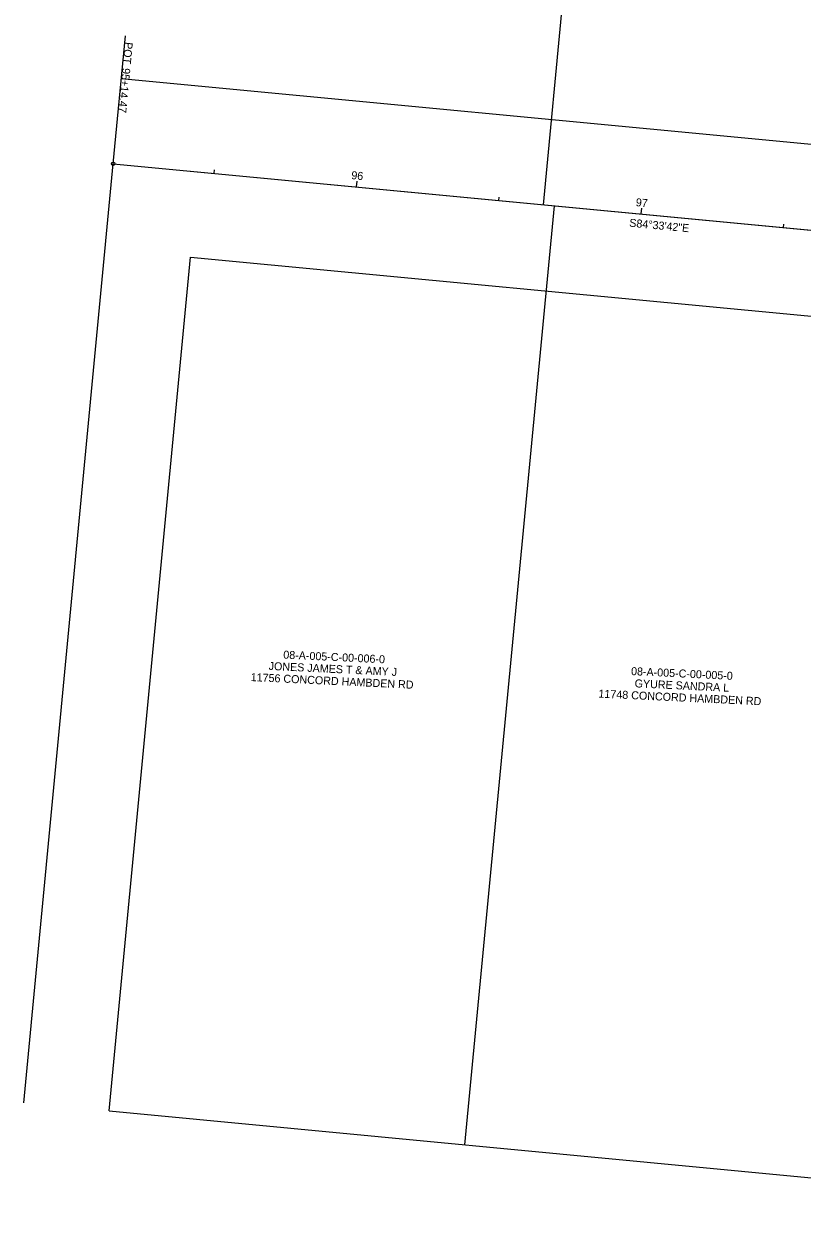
# Model space of a CAD drawing. Extents: x 2318731 to 2320621, y 732958 to 734198.
# Drawn here: x 2318820.8 to 2319093.1, y 733213.9 to 733628.7 of the extents above; entities that cross this region are included whole.
import ezdxf

# ---------------------------------------------------------------- set-up
doc = ezdxf.new("R2010")
doc.units = 0
for name, color, linetype in [('RW_X_CL_100_Bearings', 7, 'Continuous'), ('RW_X_CL_100_Cardinal_Points', 7, 'Continuous'), ('RW_X_CL_100_Stations', 7, 'Continuous'), ('RW_X_CL_500_Bearings', 7, 'Continuous'), ('RW_X_CL_500_Cardinal_Points', 7, 'Continuous'), ('RW_X_CL_500_Stations', 7, 'Continuous'), ('RW_X_Text', 7, 'Continuous'), ('SC_Scratch4', 7, 'Continuous'), ('V-SURV-IPF', 7, 'Continuous'), ('V-SURV-PARL-LINE', 7, 'Continuous'), ('V-SURV-RWAY', 7, 'Continuous')]:
    doc.layers.add(name, color=color, linetype=linetype)

msp = doc.modelspace()

# ---------------------------------------------------------------- linework, layer by layer
at = {"layer": 'RW_X_CL_100_Cardinal_Points'}
msp.add_line((2318852.08, 733579.68), (2318856.35, 733624.48), dxfattribs=at)
msp.add_circle((2318852.08, 733579.68), 0.6, dxfattribs=at)
at = {"layer": 'RW_X_CL_100_Stations'}
for p, q in [((2318887.45, 733576.32), (2318887.57, 733577.51)), ((2318937.23, 733571.58), (2318937.42, 733573.57)), ((2318987, 733566.84), (2318987.12, 733568.03)), ((2319036.78, 733562.1), (2319036.97, 733564.09)), ((2319086.55, 733557.36), (2319086.67, 733558.56))]:
    msp.add_line(p, q, dxfattribs=at)
at = {"layer": 'RW_X_CL_500_Cardinal_Points'}
msp.add_line((2318852.08, 733579.68), (2318856.35, 733624.48), dxfattribs=at)
msp.add_circle((2318852.08, 733579.68), 0.6, dxfattribs=at)
at = {"layer": 'RW_X_CL_500_Stations'}
for p, q in [((2318937.23, 733571.58), (2318937.34, 733572.77)), ((2319036.78, 733562.1), (2319036.89, 733563.3))]:
    msp.add_line(p, q, dxfattribs=at)
at = {"layer": 'SC_Scratch4'}
msp.add_lwpolyline([(2318852.08, 733579.68), (2319235.88, 733543.15), (2319306.05, 733539.81)], dxfattribs=at)
at = {"layer": 'V-SURV-IPF'}
for p, q in [((2319002.63, 733565.35), (2319030.01, 733852.93)), ((2318975.11, 733236.48), (2319006.39, 733564.99)), ((2318850.67, 733248.33), (2319212.39, 733213.89))]:
    msp.add_line(p, q, dxfattribs=at)
at = {"layer": 'V-SURV-PARL-LINE'}
for p, q in [((2318854.93, 733609.55), (2319237.97, 733573.08)), ((2318850.67, 733248.33), (2318879.11, 733546.98)), ((2318879.11, 733546.98), (2319233.74, 733513.21))]:
    msp.add_line(p, q, dxfattribs=at)
at = {"layer": 'V-SURV-RWAY'}
for p, q in [((2318820.81, 733251.17), (2318852.08, 733579.68)), ((2318852.08, 733579.68), (2319235.88, 733543.15))]:
    msp.add_line(p, q, dxfattribs=at)

# ---------------------------------------------------------------- texts
at = {"layer": 'RW_X_CL_100_Bearings'}
msp.add_text('S84°33\'42"E', height=2.8, rotation=354.5618, dxfattribs=at).set_placement((2319032.5, 733557.69))
at = {"layer": 'RW_X_CL_100_Cardinal_Points'}
for s, p in [('POT', (2318856.19, 733622.34)), ('95+14.47', (2318855.33, 733613.25))]:
    msp.add_text(s, height=2.8, rotation=264.5618, dxfattribs=at).set_placement(p)
at = {"layer": 'RW_X_CL_100_Stations'}
for s, p in [('96', (2318935.28, 733574.32)), ('97', (2319034.78, 733564.85))]:
    msp.add_text(s, height=2.8, rotation=354.5618, dxfattribs=at).set_placement(p)
at = {"layer": 'RW_X_CL_500_Bearings'}
msp.add_text('S84°33\'42"E', height=2.8, rotation=354.5618, dxfattribs=at).set_placement((2319032.5, 733557.69))
at = {"layer": 'RW_X_CL_500_Cardinal_Points'}
for s, p in [('POT', (2318856.19, 733622.34)), ('95+14.47', (2318855.33, 733613.25))]:
    msp.add_text(s, height=2.8, rotation=264.5618, dxfattribs=at).set_placement(p)
at = {"layer": 'RW_X_Text'}
for s, p in [('08-A-005-C-00-006-0', (2318911.54, 733406.57)), ('JONES JAMES T & AMY J', (2318906.43, 733402.61)), ('08-A-005-C-00-005-0', (2319033.18, 733400.79)), ('11756 CONCORD HAMBDEN RD', (2318900.14, 733398.7)), ('GYURE SANDRA L', (2319034.43, 733396.52)), ('11748 CONCORD HAMBDEN RD', (2319021.78, 733392.92))]:
    msp.add_text(s, height=2.8, rotation=357.2785, dxfattribs=at).set_placement(p)

doc.saveas('drawing.dxf')
